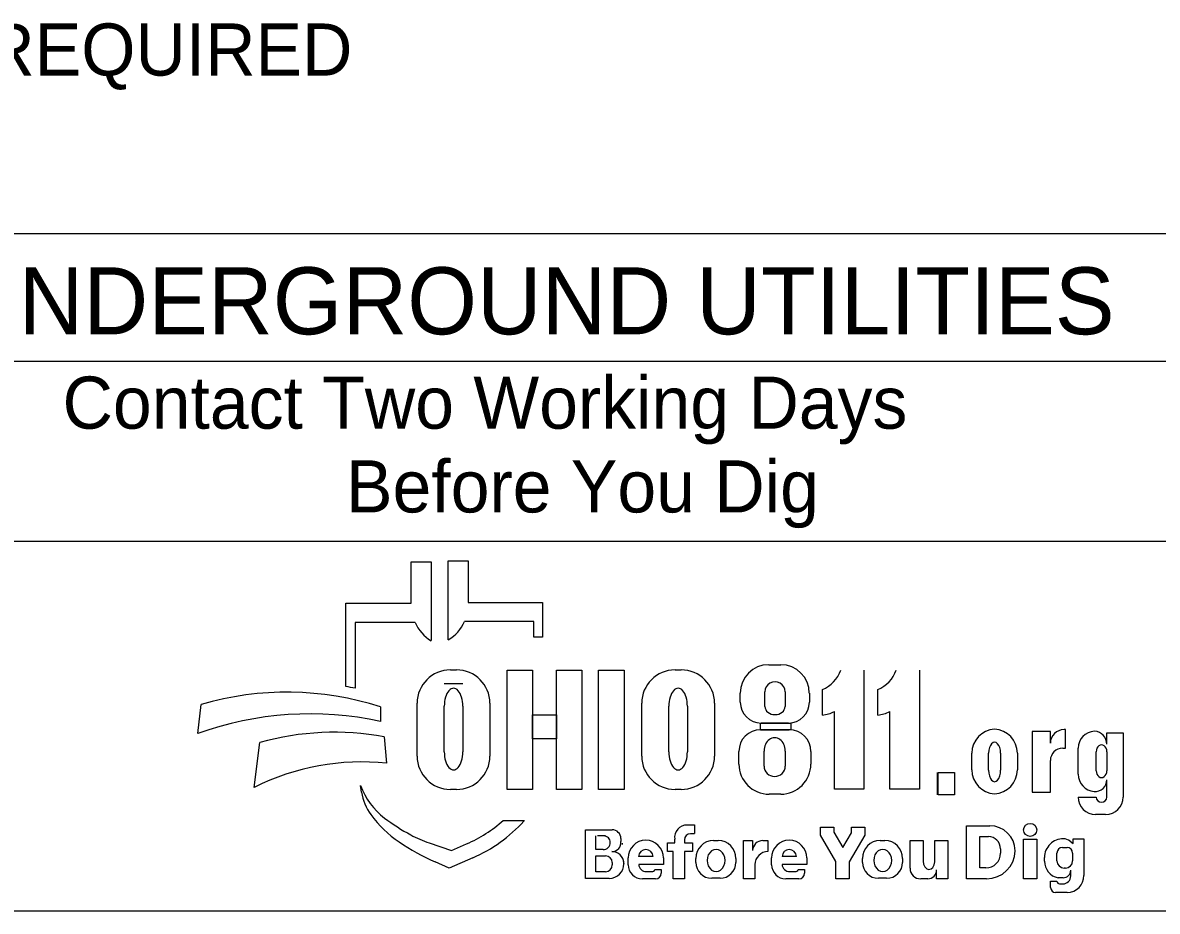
# Model space of a CAD drawing. Extents: x 0 to 34, y -1.6 to 22.
# Drawn here: x 2.69 to 5.736, y 2.661 to 5.048 of the extents above; entities that cross this region are included whole.
import ezdxf

# ---------------------------------------------------------------- set-up
doc = ezdxf.new("R2010")
doc.units = 0
doc.layers.add('SH_Data', color=7, linetype='Continuous')
doc.layers.add('SH_Text', color=7, linetype='Continuous')

msp = doc.modelspace()

# ---------------------------------------------------------------- linework, layer by layer
at = {"layer": 'SH_Data'}
for p, q in [((6.6275, 4.4803), (2.3775, 4.4803)), ((2.3775, 4.1387), (6.6275, 4.1387)), ((2.3775, 3.6553), (6.6275, 3.6553)), ((6.6275, 2.6607), (2.3775, 2.6607))]:
    msp.add_line(p, q, dxfattribs=at)
at = {"layer": 'SH_Text'}
for p, q in [((3.7335, 3.4883), (3.7335, 3.5998)), ((3.7335, 3.5998), (3.7872, 3.5998)), ((3.7872, 3.5998), (3.7872, 3.3877)), ((3.8329, 3.39), (3.8329, 3.6021)), ((3.8329, 3.6021), (3.8865, 3.6021)), ((3.8865, 3.6021), (3.8865, 3.4906)), ((3.5576, 3.2644), (3.5576, 3.4883)), ((3.5576, 3.4883), (3.7335, 3.4883)), ((3.8865, 3.4906), (4.0857, 3.4906)), ((4.0857, 3.4906), (4.0857, 3.3968)), ((3.5828, 3.4369), (3.5828, 3.26)), ((3.7439, 3.4369), (3.5828, 3.4369)), ((4.0625, 3.4392), (3.8761, 3.4392)), ((4.0625, 3.3968), (4.0625, 3.4392)), ((4.0857, 3.3968), (4.0625, 3.3968)), ((4.6931, 3.3231), (4.7258, 3.3231)), ((3.8385, 3.3091), (3.8551, 3.3091)), ((4.4416, 3.3091), (4.4581, 3.3091)), ((4.9487, 3.3087), (4.9487, 2.9887)), ((5.0975, 3.3087), (5.0975, 2.9887)), ((3.8718, 3.2721), (3.822, 3.2721)), ((4.6168, 3.2225), (4.6168, 3.2468)), ((4.683, 3.2111), (4.683, 3.2504)), ((4.7371, 3.2504), (4.7371, 3.2111)), ((4.8022, 3.2468), (4.8022, 3.2225)), ((4.8371, 3.188), (4.8371, 3.2562)), ((4.9859, 3.188), (4.9859, 3.2562)), ((3.1602, 3.1381), (3.1696, 3.2162)), ((3.6509, 3.2097), (3.6509, 3.1709)), ((3.7491, 3.0776), (3.7491, 3.2196)), ((3.822, 3.089), (3.822, 3.2114)), ((3.8718, 3.2114), (3.8718, 3.089)), ((3.9445, 3.2196), (3.9445, 3.0776)), ((4.3521, 3.0776), (4.3521, 3.2196)), ((4.425, 3.089), (4.425, 3.2114)), ((4.4748, 3.2114), (4.4748, 3.089)), ((4.5476, 3.2196), (4.5476, 3.0776)), ((4.8694, 2.9887), (4.8694, 3.1973)), ((5.0182, 2.9887), (5.0182, 3.1973)), ((4.671, 3.1482), (4.7483, 3.1482)), ((4.7462, 3.1665), (4.6728, 3.1665)), ((5.4493, 3.1436), (5.4005, 3.1436)), ((5.4005, 3.1436), (5.4005, 2.9806)), ((5.4493, 3.112), (5.4493, 3.1436)), ((5.49, 3.1487), (5.486, 3.1487)), ((5.49, 3.0989), (5.49, 3.1487)), ((5.6009, 3.1094), (5.6009, 3.1404)), ((5.6009, 3.1404), (5.6444, 3.1404)), ((5.6444, 3.1404), (5.6444, 2.9675)), ((3.312, 2.9936), (3.3267, 3.1137)), ((3.6608, 3.1291), (3.6671, 3.0582)), ((4.6131, 3.0563), (4.6131, 3.0903)), ((4.6806, 3.0503), (4.6806, 3.0912)), ((4.7374, 3.0912), (4.7374, 3.0503)), ((4.8062, 3.0903), (4.8062, 3.0563)), ((5.2385, 3.0404), (5.2385, 3.0858)), ((5.2835, 3.0396), (5.2835, 3.0858)), ((5.3157, 3.0858), (5.3157, 3.0396)), ((5.3606, 3.0858), (5.3606, 3.0404)), ((5.4823, 3.0989), (5.49, 3.0989)), ((5.5239, 3.029), (5.5239, 3.0986)), ((5.5723, 3.0383), (5.5723, 3.0893)), ((5.6009, 3.0893), (5.6009, 3.0383)), ((5.4493, 2.9806), (5.4493, 3.0659)), ((5.1456, 3.0337), (5.1456, 2.9737)), ((3.5997, 2.9807), (3.5967, 2.9986)), ((3.8551, 2.9882), (3.8385, 2.9882)), ((4.4581, 2.9882), (4.4416, 2.9882)), ((4.9487, 2.9887), (4.8694, 2.9887)), ((5.0975, 2.9887), (5.0182, 2.9887)), ((5.6009, 2.9675), (5.6009, 3.0139)), ((4.7252, 2.9753), (4.6941, 2.9753)), ((5.4005, 2.9806), (5.4493, 2.9806)), ((5.5239, 2.9675), (5.5723, 2.9675)), ((3.98, 2.9048), (4.0375, 2.9048)), ((5.5977, 2.9208), (5.5707, 2.9208)), ((4.2013, 2.749), (4.2013, 2.8798)), ((4.2013, 2.8798), (4.2725, 2.8798)), ((4.4739, 2.8926), (4.4934, 2.8926)), ((4.4934, 2.8691), (4.4832, 2.8691)), ((4.4934, 2.8926), (4.4934, 2.8696)), ((4.8319, 2.887), (4.8677, 2.887)), ((4.8319, 2.8655), (4.8319, 2.887)), ((4.8732, 2.7946), (4.8319, 2.8655)), ((4.8677, 2.887), (4.8677, 2.8734)), ((4.8677, 2.8734), (4.8918, 2.832)), ((4.8918, 2.832), (4.9151, 2.8719)), ((4.9509, 2.8655), (4.9088, 2.7932)), ((4.9151, 2.8719), (4.9151, 2.887)), ((4.9151, 2.887), (4.9509, 2.887)), ((4.9509, 2.887), (4.9509, 2.8655)), ((5.2243, 2.8906), (5.2866, 2.8906)), ((5.2243, 2.7478), (5.2243, 2.8906)), ((3.7816, 2.8444), (3.841, 2.8239)), ((3.841, 2.8239), (3.8821, 2.8417)), ((4.2293, 2.8263), (4.2293, 2.8632)), ((4.2545, 2.8632), (4.2332, 2.8632)), ((4.2963, 2.856), (4.2963, 2.8481)), ((4.4213, 2.8212), (4.4213, 2.8442)), ((4.4213, 2.8442), (4.4406, 2.8442)), ((4.4406, 2.8442), (4.4406, 2.8546)), ((4.4667, 2.8526), (4.4667, 2.8442)), ((4.4667, 2.8442), (4.4883, 2.8442)), ((4.4883, 2.8442), (4.4883, 2.8212)), ((4.5451, 2.8508), (4.5573, 2.8508)), ((4.6254, 2.7478), (4.6254, 2.8505)), ((4.6254, 2.8505), (4.6499, 2.8505)), ((4.6499, 2.8505), (4.6499, 2.8237)), ((4.6772, 2.8505), (4.691, 2.8505)), ((4.691, 2.8505), (4.691, 2.8209)), ((4.9925, 2.8508), (5.0047, 2.8508)), ((5.0727, 2.8508), (5.1075, 2.8508)), ((5.0727, 2.7762), (5.0727, 2.8508)), ((5.1075, 2.8508), (5.1075, 2.7954)), ((5.1388, 2.7938), (5.1388, 2.8508)), ((5.1388, 2.8508), (5.1736, 2.8508)), ((5.1736, 2.8508), (5.1736, 2.7478)), ((5.2603, 2.7773), (5.2603, 2.8613)), ((5.2603, 2.8613), (5.2828, 2.8613)), ((5.377, 2.8549), (5.4126, 2.8549)), ((5.377, 2.7478), (5.377, 2.8549)), ((5.4126, 2.8549), (5.4126, 2.7478)), ((5.5021, 2.8493), (5.5107, 2.8427)), ((5.5107, 2.8553), (5.5395, 2.8553)), ((5.5107, 2.8427), (5.5107, 2.8553)), ((5.5107, 2.8553), (5.5395, 2.8553)), ((5.5395, 2.8553), (5.5395, 2.7567)), ((3.8983, 2.8044), (3.835, 2.7769)), ((4.2487, 2.8263), (4.2293, 2.8263)), ((4.2293, 2.7669), (4.2293, 2.8097)), ((4.2293, 2.8097), (4.2548, 2.8097)), ((4.3159, 2.7858), (4.3159, 2.8042)), ((4.3824, 2.8082), (4.3439, 2.8082)), ((4.4104, 2.8042), (4.4104, 2.7866)), ((4.4362, 2.8212), (4.4213, 2.8212)), ((4.4362, 2.7478), (4.4362, 2.8212)), ((4.4883, 2.8212), (4.4667, 2.8212)), ((4.4667, 2.8212), (4.4667, 2.7478)), ((4.4973, 2.7922), (4.4973, 2.8029)), ((4.6051, 2.8029), (4.6051, 2.7922)), ((4.7008, 2.7858), (4.7008, 2.8042)), ((4.7674, 2.8082), (4.7288, 2.8082)), ((4.7953, 2.8042), (4.7953, 2.7866)), ((4.9447, 2.7922), (4.9447, 2.8029)), ((5.0525, 2.8029), (5.0525, 2.7922)), ((5.3154, 2.8286), (5.3154, 2.8168)), ((5.4335, 2.7953), (5.4335, 2.8054)), ((5.467, 2.7961), (5.467, 2.8173)), ((5.4816, 2.8319), (5.4944, 2.8319)), ((5.509, 2.8173), (5.509, 2.7961)), ((3.835, 2.7769), (3.7976, 2.7934)), ((4.2729, 2.7916), (4.2729, 2.7853)), ((4.3043, 2.7887), (4.3043, 2.7884)), ((4.4104, 2.7866), (4.344, 2.7866)), ((4.3876, 2.7729), (4.4045, 2.7729)), ((4.4045, 2.7729), (4.4045, 2.7631)), ((4.6559, 2.786), (4.6559, 2.7478)), ((4.7953, 2.7866), (4.7289, 2.7866)), ((4.7725, 2.7729), (4.7894, 2.7729)), ((4.7894, 2.7729), (4.7894, 2.7631)), ((4.8732, 2.7478), (4.8732, 2.7946)), ((4.9088, 2.7932), (4.9088, 2.7478)), ((5.2759, 2.7773), (5.2603, 2.7773)), ((5.4897, 2.7768), (5.4863, 2.7768)), ((4.265, 2.749), (4.2013, 2.749)), ((4.2546, 2.7669), (4.2293, 2.7669)), ((4.3892, 2.7478), (4.3538, 2.7478)), ((4.3649, 2.7673), (4.379, 2.7673)), ((4.4667, 2.7478), (4.4362, 2.7478)), ((4.5623, 2.7494), (4.5401, 2.7494)), ((4.6559, 2.7478), (4.6254, 2.7478)), ((4.7742, 2.7478), (4.7388, 2.7478)), ((4.7498, 2.7673), (4.7639, 2.7673)), ((4.9088, 2.7478), (4.8732, 2.7478)), ((5.0097, 2.7494), (4.9875, 2.7494)), ((5.1199, 2.7478), (5.1011, 2.7478)), ((5.1439, 2.7478), (5.1439, 2.7719)), ((5.1736, 2.7478), (5.1439, 2.7478)), ((5.2779, 2.7478), (5.2243, 2.7478)), ((5.4126, 2.7478), (5.377, 2.7478)), ((5.45, 2.7245), (5.45, 2.7415)), ((5.45, 2.7415), (5.467, 2.7415)), ((5.4835, 2.7506), (5.4698, 2.7506)), ((5.5039, 2.7557), (5.5039, 2.7711)), ((5.4942, 2.7114), (5.4631, 2.7114)), ((5.4738, 2.7345), (5.4827, 2.7345))]:
    msp.add_line(p, q, dxfattribs=at)
for points in [[(3.991, 3.3081), (4.0589, 3.3081), (4.0589, 2.9881), (3.991, 2.9881)], [(4.1231, 3.3081), (4.1911, 3.3081), (4.1911, 2.9881), (4.1231, 2.9881)], [(4.2364, 3.3081), (4.3052, 3.3081), (4.3052, 2.9881), (4.2364, 2.9881)], [(4.0589, 3.1882), (4.1231, 3.1882), (4.1231, 3.1242), (4.0589, 3.1242)], [(4.6706, 3.1665), (4.7523, 3.1665), (4.7523, 3.1481), (4.6706, 3.1481)], [(5.148, 3.0337), (5.1921, 3.0337), (5.1921, 2.9737), (5.148, 2.9737)]]:
    msp.add_lwpolyline(points, close=True, dxfattribs=at)
msp.add_circle((5.3952, 2.8793), 0.0177, dxfattribs=at)
for centre, radius, start, end in [((3.8353, 3.4736), 0.0985, 201.9296, 240.7469), ((3.7847, 3.476), 0.0985, 299.2531, 338.0704), ((4.6931, 3.2468), 0.0763, 90, 180), ((4.7258, 3.2468), 0.0763, 0, 90), ((3.8385, 3.2196), 0.0895, 90, 180), ((3.8551, 3.2196), 0.0895, 0, 90), ((4.4416, 3.2196), 0.0895, 90, 180), ((4.4581, 3.2196), 0.0895, 0, 90), ((4.8031, 3.3379), 0.0885, 292.5572, 340.7355), ((4.952, 3.3379), 0.0885, 292.5572, 340.7355), ((3.4295, 2.4554), 0.8191, 79.2074, 81.0007), ((3.3997, 2.4302), 0.8191, 72.1402, 106.3144), ((4.6728, 3.2225), 0.056, 180, 270), ((4.7462, 3.2225), 0.056, 270, 0), ((3.4628, 2.2991), 0.8919, 77.8238, 109.8274), ((4.8291, 3.2761), 0.0885, 275.1733, 297.0931), ((4.9779, 3.2761), 0.0885, 275.1733, 297.0931), ((3.5267, 2.4094), 0.7322, 79.44, 105.8467), ((4.671, 3.0903), 0.0579, 90, 180), ((4.7483, 3.0903), 0.0579, 0, 90), ((5.3024, 3.0858), 0.064, 92.5886, 180), ((5.2967, 3.0858), 0.064, 0, 87.4114), ((5.486, 3.112), 0.0367, 90, 180), ((5.5698, 3.0986), 0.0459, 92.6865, 180), ((5.5658, 3.1094), 0.0351, 0, 86.9262), ((3.8385, 3.0776), 0.0895, 180, 270), ((3.8551, 3.0776), 0.0895, 270, 0), ((4.4416, 3.0776), 0.0895, 180, 270), ((4.4581, 3.0776), 0.0895, 270, 0), ((5.4823, 3.0659), 0.033, 90, 180), ((3.5987, 2.4262), 0.6357, 83.8248, 116.8021), ((4.6941, 3.0563), 0.081, 180, 270), ((4.7252, 3.0563), 0.081, 270, 0), ((5.3024, 3.0404), 0.064, 180, 267.4114), ((5.2967, 3.0404), 0.064, 272.5886, 0), ((5.5702, 3.029), 0.0463, 180, 265.7132), ((3.7841, 3.0707), 0.2008, 201.0457, 232.5314), ((5.5696, 3.0139), 0.0313, 264.7825, 0), ((3.741, 3.0048), 0.1433, 189.6817, 216.0884), ((5.5707, 2.9675), 0.0468, 180, 270), ((5.5977, 2.9675), 0.0468, 270, 0), ((3.8747, 3.1022), 0.3088, 216.0884, 235.7167), ((3.9766, 3.3219), 0.5173, 232.5314, 241.794), ((3.7387, 3.1722), 0.3602, 293.4582, 312.0712), ((3.7387, 3.1722), 0.401, 293.4582, 317.8286), ((3.8914, 3.1631), 0.3371, 241.794, 250.9821), ((4.2725, 2.856), 0.0238, 0, 90), ((4.4739, 2.859), 0.0335, 90, 187.5187), ((4.4832, 2.8526), 0.0165, 90, 180), ((5.2866, 2.8223), 0.0682, 0.9944, 90), ((4.0412, 3.3465), 0.6044, 235.7167, 246.2325), ((4.2487, 2.845), 0.0187, 270, 2.0582), ((4.2505, 2.8463), 0.0169, 357.8325, 90), ((4.2721, 2.8453), 0.0243, 270, 6.6529), ((4.2827, 2.8438), 0.0175, 347.4023, 0), ((4.3631, 2.8042), 0.0473, 0, 180), ((4.5451, 2.8029), 0.0478, 90, 180), ((4.5573, 2.8029), 0.0478, 0, 90), ((4.6768, 2.8237), 0.0269, 89.2449, 180), ((4.7481, 2.8042), 0.0473, 0, 180), ((4.9925, 2.8029), 0.0478, 90, 180), ((5.0047, 2.8029), 0.0478, 0, 90), ((5.2828, 2.8286), 0.0327, 0, 90), ((5.4834, 2.8054), 0.0499, 89.0934, 180), ((5.4848, 2.827), 0.0283, 52.1415, 91.2046), ((4.2548, 2.7916), 0.0181, 0, 90), ((4.2722, 2.7889), 0.0321, 4.0748, 90), ((4.3632, 2.8072), 0.0193, 2.9632, 177.0368), ((4.6908, 2.786), 0.0349, 89.6033, 180), ((4.7481, 2.8072), 0.0193, 2.9632, 177.0368), ((5.2759, 2.8168), 0.0395, 270, 0), ((5.2779, 2.8248), 0.0769, 270, 359.0635), ((5.4816, 2.8173), 0.0146, 90, 180), ((5.4944, 2.8173), 0.0146, 0, 90), ((4.2546, 2.7853), 0.0184, 270, 0), ((4.265, 2.7884), 0.0393, 270, 0), ((4.2714, 2.7887), 0.033, 0, 11.7502), ((4.3538, 2.7858), 0.038, 180, 270), ((4.3649, 2.7883), 0.021, 184.827, 270), ((4.379, 2.7767), 0.00938, 270, 335.9979), ((4.5401, 2.7922), 0.0428, 180, 270), ((4.5623, 2.7922), 0.0428, 270, 0), ((4.7388, 2.7858), 0.038, 180, 270), ((4.7498, 2.7883), 0.021, 184.827, 270), ((4.7639, 2.7767), 0.00938, 270, 335.9979), ((4.9875, 2.7922), 0.0428, 180, 270), ((5.0097, 2.7922), 0.0428, 270, 0), ((5.1011, 2.7762), 0.0284, 180, 270), ((5.4791, 2.7953), 0.0457, 180, 258.2203), ((5.4863, 2.7961), 0.0193, 180, 270), ((5.4897, 2.7961), 0.0193, 270, 0), ((4.3892, 2.7631), 0.0152, 270, 0), ((4.7742, 2.7631), 0.0152, 270, 0), ((5.1199, 2.7719), 0.024, 270, 0), ((5.4827, 2.7557), 0.0212, 270, 0), ((5.4835, 2.771), 0.0203, 270, 0), ((5.4942, 2.7567), 0.0453, 270, 0), ((5.4631, 2.7245), 0.0131, 180, 270), ((5.4738, 2.7413), 0.00682, 180, 270)]:
    msp.add_arc(centre, radius, start, end, dxfattribs=at)
for centre, major_axis, ratio, start_param, end_param in [((3.8469, 3.2114), (0, 0.0484), 0.514403, 4.712389, 7.853982), ((4.4499, 3.2114), (0, 0.0484), 0.514403, 4.712389, 7.853982), ((4.71, 3.2504), (0.0271, 0), 0.969373, 0, 3.141593), ((4.71, 3.2111), (0.0271, 0), 0.818453, 3.141593, 6.283185), ((4.709, 3.0912), (0, 0.0358), 0.794529, 4.712389, 7.853982), ((5.2996, 3.0858), (0, 0.0291), 0.553236, 4.712389, 7.853982), ((5.5866, 3.0893), (0, 0.0184), 0.777179, 4.712389, 7.853982), ((3.8469, 3.089), (0, 0.0484), 0.514403, 1.570796, 4.712389), ((4.4499, 3.089), (0, 0.0484), 0.514403, 1.570796, 4.712389), ((4.709, 3.0503), (0.0284, 0), 0.959837, 3.141593, 6.283185), ((5.2996, 3.0396), (0, 0.0308), 0.522014, 1.570796, 4.712389), ((5.5866, 3.0383), (0, 0.0184), 0.777179, 1.570796, 4.712389), ((5.5866, 2.9675), (0.0143, 0), 0.959012, 3.141593, 6.283185), ((4.5517, 2.7976), (0, 0.029), 0.832186, 4.712389, 7.853982), ((4.9991, 2.7976), (0, 0.029), 0.832186, 4.712389, 7.853982), ((4.5517, 2.7976), (0, 0.0302), 0.797287, 1.570796, 4.712389), ((4.9991, 2.7976), (0, 0.0302), 0.797287, 1.570796, 4.712389), ((5.1231, 2.7962), (-0.0011, 0.0231), 0.679042, 1.570796, 4.575961)]:
    msp.add_ellipse(centre, major_axis=major_axis, ratio=ratio, start_param=start_param, end_param=end_param, dxfattribs=at)

# ---------------------------------------------------------------- texts
for s, height, p in [('NONE REQUIRED', 0.14, (1.9944, 4.9056)), ('UNDERGROUND UTILITIES', 0.18, (2.5057, 4.2106)), ('Contact Two Working Days', 0.14, (2.7972, 3.9571)), ('Before You Dig', 0.14, (3.5583, 3.7321))]:
    msp.add_text(s, height=height, dxfattribs=at).set_placement(p)

doc.saveas('drawing.dxf')
